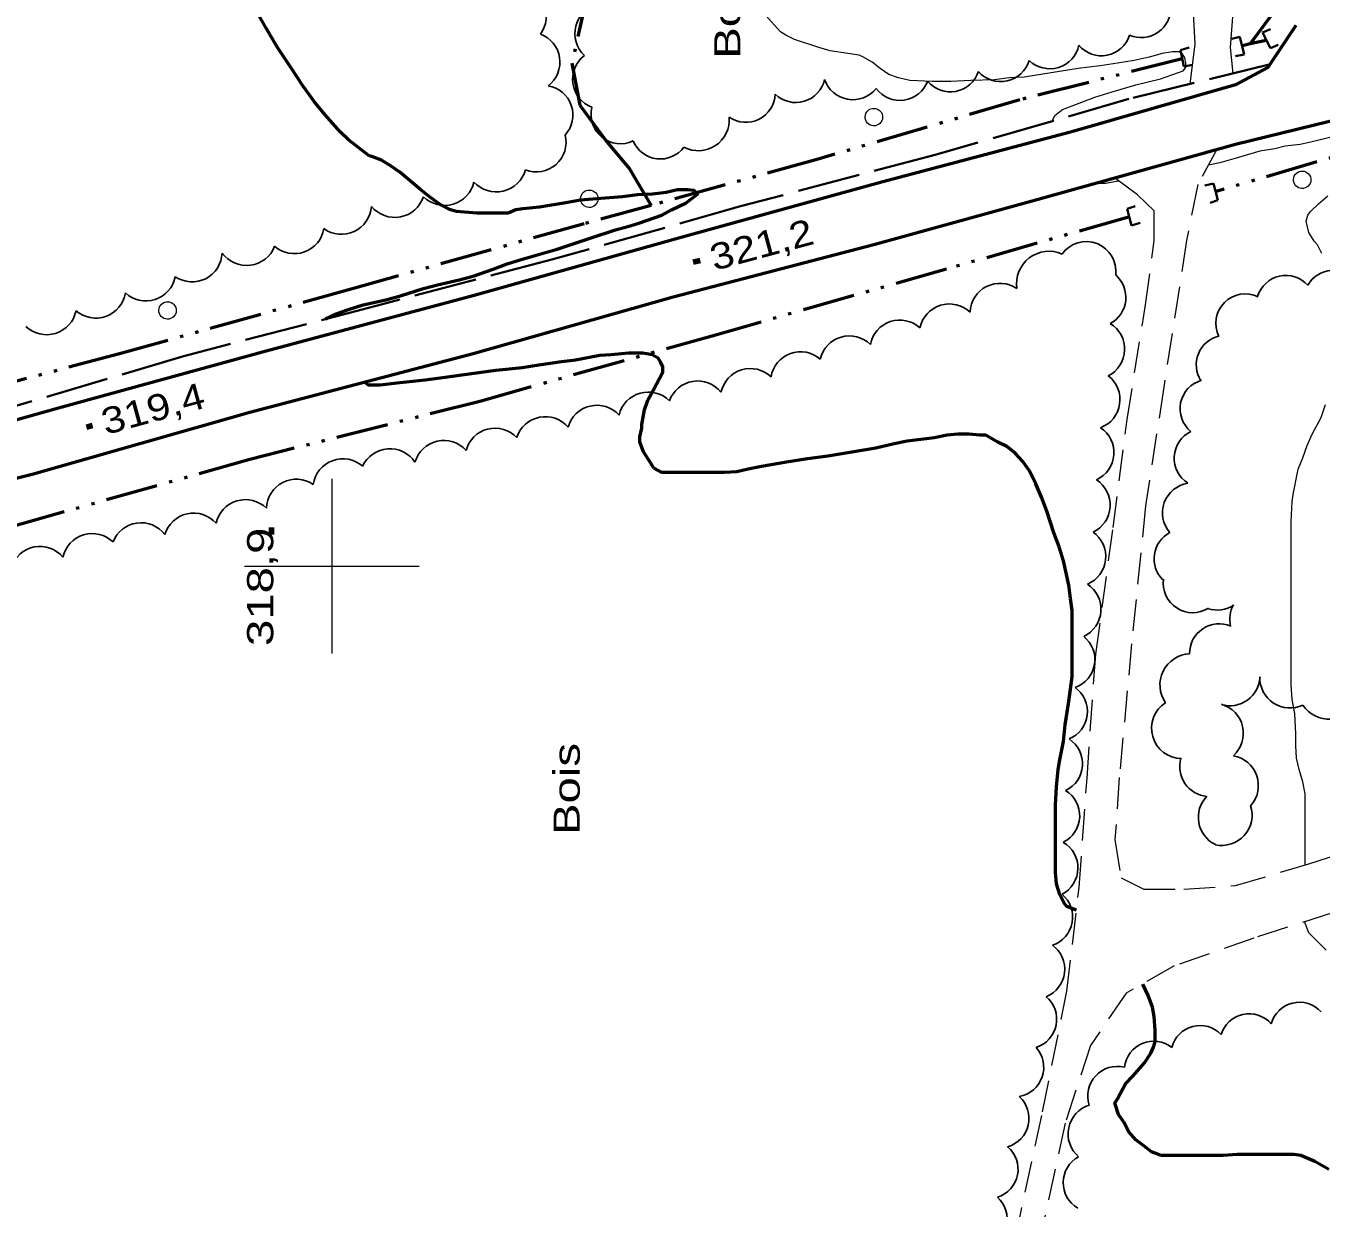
# Model space of a CAD drawing. Extents: x 240591 to 242335, y 5323482 to 5326937.
# Drawn here: x 240765 to 240913.3, y 5324526.5 to 5324661.9 of the extents above; entities that cross this region are included whole.
import ezdxf
from ezdxf.enums import TextEntityAlignment as Align

# ---------------------------------------------------------------- set-up
doc = ezdxf.new("R2010")
doc.units = 0
doc.header["$LTSCALE"] = 1.2
for name, pattern in [('DASH_DOUBLE_DOT', [9.2, 5, -1.2, 0.3, -1.2, 0.3, -1.2]), ('LONG_DASHED', [7.5, 6, -1.5]), ('MEDIUM_DASHED', [4.5, 3, -1.5])]:
    doc.linetypes.add(name, pattern=pattern)
for name, color, linetype, lineweight in [('1', 7, 'Continuous', 53), ('19', 7, 'Continuous', 13), ('2', 7, 'Continuous', 13), ('21', 7, 'Continuous', 53), ('26', 7, 'Continuous', 35), ('3', 7, 'Continuous', 140), ('36', 7, 'Continuous', 13), ('4', 7, 'DASH_DOUBLE_DOT', 53), ('44', 7, 'Continuous', 25), ('61', 7, 'Continuous', 13)]:
    doc.layers.add(name, color=color, linetype=linetype, lineweight=lineweight)

msp = doc.modelspace()

# ---------------------------------------------------------------- linework, layer by layer
at = {"layer": '1', "linetype": 'LONG_DASHED'}
for points in [[(240804.3, 5324647), (240801.9, 5324648.8), (240801, 5324649.7), (240799.2, 5324651.7), (240798, 5324653.2), (240796.7, 5324655), (240795.3, 5324657.1), (240793.8, 5324659.4), (240792.5, 5324661.6), (240790.8, 5324664.6)], [(240821.1, 5324640.8), (240820.2, 5324640.4), (240819.5, 5324640.4), (240816.6, 5324640.4), (240814.3, 5324640.6), (240813.6, 5324640.8), (240812.4, 5324641.4), (240811.3, 5324642.2), (240810.2, 5324643.1), (240807.8, 5324645.1), (240806.8, 5324645.8), (240805.7, 5324646.5), (240804.6, 5324646.9), (240804.3, 5324647)], [(240884.8, 5324591.9), (240884.8, 5324594.9), (240884.6, 5324596.3), (240884.4, 5324597.8), (240883.8, 5324600.6), (240883.3, 5324602.2), (240882.7, 5324603.8), (240881.9, 5324606.3), (240881.3, 5324607.9), (240880.6, 5324609.5), (240879.9, 5324610.9), (240879.1, 5324612), (240878.3, 5324612.9), (240877.3, 5324613.7), (240876.3, 5324614.2), (240874.9, 5324615), (240874.2, 5324615), (240873, 5324615.1), (240871.7, 5324615.1), (240870.5, 5324615), (240869, 5324614.7), (240865.9, 5324614.3), (240864.4, 5324614), (240862.3, 5324613.5), (240859.8, 5324613.1), (240856.8, 5324612.6), (240854.5, 5324612.3), (240852.1, 5324611.9), (240849.2, 5324611.4), (240847.7, 5324611.1), (240846.4, 5324610.8), (240845, 5324610.7), (240843.6, 5324610.7), (240840.6, 5324610.7), (240837.8, 5324610.7), (240836.9, 5324611.2), (240836.6, 5324611.7), (240835.7, 5324613.1), (240835.3, 5324614.2), (240835.3, 5324614.8), (240835.5, 5324615.8), (240835.5, 5324616.2)], [(240914.2, 5324530.9), (240912.6, 5324531.8), (240911, 5324532.5), (240910.2, 5324532.6), (240909.3, 5324532.6), (240906.6, 5324532.6), (240903.7, 5324532.6), (240902.1, 5324532.5), (240900.6, 5324532.5), (240897.8, 5324532.5), (240895, 5324532.5), (240894.5, 5324532.7), (240893.9, 5324532.9), (240893, 5324533.6), (240892.1, 5324534.3), (240891.3, 5324535.2), (240890.7, 5324536.3), (240890.1, 5324537.2)]]:
    msp.add_lwpolyline(points, dxfattribs=at)
at = {"layer": '1'}
for points in [[(240799.3, 5324628.3), (240800.5, 5324628.9), (240801.9, 5324629.4), (240803.6, 5324629.9), (240806.2, 5324630.5), (240808, 5324631), (240810.5, 5324631.8), (240812.1, 5324632.2), (240814.6, 5324632.8), (240816.2, 5324633.2), (240818.5, 5324634), (240820.1, 5324634.6), (240821.7, 5324635.1), (240823.4, 5324635.6), (240825.8, 5324636.3), (240827.3, 5324636.8), (240829.7, 5324637.6), (240832.5, 5324638.5), (240833.9, 5324638.9), (240835.3, 5324639.3), (240837.8, 5324640.2), (240838.9, 5324640.8), (240840.6, 5324641.6), (240841.9, 5324642.6), (240841.5, 5324643), (240840.8, 5324643.1), (240839.6, 5324643.1), (240838.3, 5324642.8), (240836.7, 5324642.6), (240835, 5324642.5), (240833.3, 5324642.3), (240830.8, 5324642.1), (240828.5, 5324641.9), (240826.8, 5324641.6), (240823.8, 5324641.1), (240821.9, 5324640.9), (240821.1, 5324640.8)], [(240826.3, 5324623.4), (240823.7, 5324623), (240821.8, 5324622.7), (240818.8, 5324622.4), (240816, 5324622), (240813, 5324621.6), (240810.7, 5324621.3), (240807.8, 5324621), (240805.5, 5324620.7), (240804.2, 5324620.7), (240803.7, 5324621.1)], [(240835.5, 5324616.2), (240835.8, 5324617.9), (240836.2, 5324619), (240836.8, 5324620.1), (240837.9, 5324622.2), (240837.9, 5324622.8), (240837.7, 5324623.3), (240837.4, 5324623.8), (240836.7, 5324624.2), (240836.1, 5324624.3), (240835.6, 5324624.4), (240834, 5324624.4), (240832, 5324624.2), (240830.7, 5324624.1), (240827.9, 5324623.6), (240826.3, 5324623.4)], [(240885.3, 5324560.6), (240884.2, 5324561), (240883.9, 5324561.4), (240883.4, 5324562.4), (240883, 5324563.6), (240882.9, 5324564.9), (240882.9, 5324566.7), (240882.9, 5324569.5), (240882.9, 5324572.6), (240883, 5324574.7), (240883.2, 5324576.7), (240883.4, 5324577.8), (240883.8, 5324579.9), (240884, 5324581.8), (240884.4, 5324584.5), (240884.8, 5324587.3), (240884.8, 5324588.8), (240884.8, 5324591.6), (240884.8, 5324591.9)], [(240890.1, 5324537.2), (240889.7, 5324538.5), (240890, 5324539), (240890.9, 5324540.7), (240891.8, 5324541.6), (240893.1, 5324543.1), (240893.8, 5324544.2), (240894.1, 5324544.9), (240894.3, 5324545.5), (240894.3, 5324546.8), (240894.2, 5324548.4), (240894, 5324549.5), (240893.5, 5324550.8), (240892.9, 5324552.1)]]:
    msp.add_lwpolyline(points, dxfattribs=at)
at = {"layer": '19'}
msp.add_lwpolyline([(240898.3, 5324655.2), (240898.9, 5324659.8), (240898.6, 5324665.5), (240903.4, 5324666), (240902.9, 5324659.4), (240903.2, 5324656.4)], dxfattribs=at)
at = {"layer": '19', "linetype": 'MEDIUM_DASHED'}
for points in [[(240901.4, 5324647.8), (240899.2, 5324643.7), (240897.9, 5324637.3), (240895.3, 5324620.5), (240893.2, 5324606.9), (240891.6, 5324591.1), (240890.2, 5324575.8), (240889.7, 5324568.7), (240890.4, 5324564.3), (240893, 5324563), (240897.6, 5324563), (240903.5, 5324563.4), (240911.9, 5324565.9), (240921.9, 5324569.1)], [(240857.3, 5324402.1), (240859.2, 5324416.9), (240860.8, 5324430.9), (240861.2, 5324443.5), (240863.4, 5324457.3), (240866.1, 5324468.8), (240868.9, 5324481.2), (240872.2, 5324493.8), (240875.2, 5324506.7), (240878.3, 5324523), (240881.4, 5324537.5), (240884.2, 5324551.3), (240885.6, 5324563.2), (240886.5, 5324575.7), (240887.5, 5324589.9), (240889.5, 5324604.4), (240891.1, 5324616.8), (240893.2, 5324629.9), (240894.2, 5324637.3), (240894.2, 5324640.7), (240892.3, 5324642.5), (240889.6, 5324644.5)], [(240938.5, 5324566.7), (240926.7, 5324563.8), (240914.6, 5324560.3), (240905.6, 5324557.4), (240896.5, 5324554.2), (240891, 5324551.1), (240886.9, 5324545.1), (240884, 5324536.2), (240881.6, 5324525.1), (240879.4, 5324512.5), (240878, 5324503.1), (240876.1, 5324494.7), (240873.2, 5324483.1), (240872.2, 5324473.4), (240870.9, 5324466.3), (240867.9, 5324457.5), (240865.7, 5324445.8), (240864.5, 5324432.3), (240863.1, 5324419.4), (240861.1, 5324406.3)]]:
    msp.add_lwpolyline(points, dxfattribs=at)
at = {"layer": '2'}
for points in [[(240882.7, 5324651), (240882.6, 5324651.1), (240882.8, 5324651.6), (240883.2, 5324651.9), (240883.7, 5324652.3), (240884.8, 5324652.7), (240887.4, 5324653.7), (240889.4, 5324654.3), (240892.1, 5324655.1), (240894.9, 5324655.8), (240897.5, 5324656.7), (240897.8, 5324657.1), (240897.8, 5324657.6), (240897.7, 5324658.2), (240897.4, 5324658.7), (240897, 5324658.9), (240896.3, 5324658.9), (240895.1, 5324658.7), (240893.6, 5324658.3), (240891.9, 5324657.9), (240890, 5324657.6), (240888, 5324657.3), (240885.5, 5324657), (240882.4, 5324656.5), (240879.3, 5324656), (240877.6, 5324655.9), (240875.9, 5324655.7), (240873.2, 5324655.6), (240870.9, 5324655.5), (240868.8, 5324655.5), (240866.2, 5324655.6), (240864.9, 5324655.9), (240863.8, 5324656.3), (240862.8, 5324657), (240861.9, 5324657.7), (240860.9, 5324658.3), (240860.4, 5324658.5), (240859.1, 5324658.7), (240857.1, 5324659), (240855.8, 5324659.4), (240853, 5324660.3), (240852, 5324660.8), (240851.4, 5324661.2), (240851, 5324661.6), (240849.4, 5324663.4)], [(240914.3, 5324649.1), (240912.3, 5324648.6), (240910.9, 5324648.3), (240909.2, 5324648.1), (240908, 5324647.8), (240906.3, 5324647.5)], [(240906.3, 5324647.5), (240903.6, 5324646.7), (240901.7, 5324646.2), (240900.4, 5324645.9)], [(240890.1, 5324644.1), (240888.6, 5324643.8), (240887.2, 5324643.8)], [(240913.4, 5324635.8), (240912.9, 5324636.8), (240912.5, 5324637.2), (240911.9, 5324638.2), (240911.6, 5324639.5), (240911.8, 5324640.2), (240912.1, 5324640.6), (240913, 5324641.5), (240914.1, 5324642.4)], [(240911.5, 5324565.8), (240911.5, 5324568.8), (240911.5, 5324571.3), (240911.5, 5324573.9), (240911.2, 5324575.3), (240910.8, 5324576.7), (240910.5, 5324578), (240910.4, 5324579.4), (240910.4, 5324580.8), (240910.3, 5324583.1), (240910, 5324584.7), (240909.9, 5324586.4), (240909.9, 5324588.1), (240909.9, 5324591.1), (240909.9, 5324593.7), (240909.9, 5324596.9), (240909.9, 5324599.6), (240909.9, 5324602.5), (240909.9, 5324605.1), (240910, 5324607.4), (240910.1, 5324608.2), (240910.7, 5324611.1), (240911.2, 5324612.4), (240911.7, 5324613.8), (240912.3, 5324615.1), (240913.3, 5324617), (240913.8, 5324618.5)], [(240913.9, 5324556), (240911.9, 5324558), (240911.4, 5324559.3)]]:
    msp.add_lwpolyline(points, dxfattribs=at)
at = {"layer": '21'}
for points in [[(240910.4, 5324661.9), (240907.2, 5324657.1), (240903.5, 5324655.1), (240884.6, 5324649.7), (240863.1, 5324644), (240840.3, 5324637.7), (240816.3, 5324631), (240792.5, 5324624.6), (240768.7, 5324618.1), (240744.5, 5324611.3), (240717.6, 5324604), (240694.3, 5324597.5), (240669.7, 5324591), (240649, 5324585.6), (240630.8, 5324580.6), (240610.8, 5324574.8)], [(240941.8, 5324658.1), (240924.9, 5324653.5), (240903.5, 5324648.3), (240880.9, 5324642), (240862.1, 5324636.8), (240839.1, 5324630.8), (240816.2, 5324624.3), (240790.6, 5324617.6), (240765.7, 5324610.5), (240737.8, 5324603.5), (240706.7, 5324594.4), (240678.6, 5324586.6), (240650.6, 5324578.9), (240620.6, 5324570.1), (240610.8, 5324567.5)]]:
    msp.add_lwpolyline(points, dxfattribs=at)
at = {"layer": '21', "linetype": 'LONG_DASHED', "lineweight": 35}
msp.add_lwpolyline([(240907.5, 5324657.5), (240891.3, 5324653.5), (240869.1, 5324647.1), (240846.8, 5324641.2), (240825.2, 5324635.1), (240805.8, 5324630), (240782.9, 5324624), (240763.7, 5324618.3), (240745.5, 5324613.4), (240728.3, 5324608.7), (240710.6, 5324603.9), (240687, 5324597.4), (240666.3, 5324592), (240647.4, 5324587), (240631.1, 5324582.9), (240614.9, 5324578.2), (240610.8, 5324577.1)], dxfattribs=at)
at = {"layer": '26'}
for p, q in [((240904, 5324660.6), (240903.1, 5324660.4)), ((240904, 5324660.6), (240904.5, 5324658.6)), ((240906.6, 5324661.1), (240907.5, 5324661.5)), ((240907.5, 5324659.3), (240906.6, 5324661.1)), ((240897.2, 5324659.1), (240898.2, 5324659.4)), ((240897.6, 5324657.2), (240897.2, 5324659.1)), ((240907.5, 5324659.3), (240908.4, 5324659.7)), ((240904.5, 5324658.6), (240903.5, 5324658.4)), ((240897.6, 5324657.2), (240898.6, 5324657.4)), ((240901, 5324643.8), (240900, 5324643.6)), ((240901, 5324643.8), (240901.5, 5324641.9)), ((240891.1, 5324640.9), (240892, 5324641.2)), ((240901.5, 5324641.9), (240900.6, 5324641.6)), ((240891.6, 5324639), (240891.1, 5324640.9)), ((240891.6, 5324639), (240892.6, 5324639.3))]:
    msp.add_line(p, q, dxfattribs=at)
at = {"layer": '3'}
for p, q in [((240841.4, 5324634.8), (240842.2, 5324635)), ((240771.9, 5324615.9), (240772.6, 5324616.1)), ((240793.1, 5324603.6), (240793.1, 5324604.4))]:
    msp.add_line(p, q, dxfattribs=at)
at = {"layer": '36'}
for centre in [(240862.093, 5324651.42), (240911.143, 5324644.24), (240829.493, 5324642.07), (240781.193, 5324629.27)]:
    msp.add_ellipse(centre, major_axis=(0.23, 0.973), ratio=0.999999, dxfattribs=at)
at = {"layer": '4'}
msp.add_line((240923.4, 5324649.4), (240901.3, 5324642.9), dxfattribs=at)
for points in [[(240838.1, 5324695.3), (240833.5, 5324685.9), (240831.9, 5324674.9), (240829.5, 5324666.5), (240827.5, 5324657.6), (240828.4, 5324652.8), (240831.5, 5324648.6), (240834.1, 5324645.5), (240836.6, 5324641.3)], [(240907.9, 5324673.3), (240909, 5324667.1), (240908.6, 5324664.4), (240905.2, 5324659.8)], [(240907, 5324660.2), (240905.2, 5324659.8), (240904.3, 5324659.6)], [(240897.4, 5324658.1), (240878.8, 5324653.4), (240855.7, 5324646.6), (240836.6, 5324641.3)], [(240836.6, 5324641.3), (240828.9, 5324639.2), (240802.5, 5324631.8), (240775.7, 5324624.3), (240749.7, 5324617.4), (240726.6, 5324610.7), (240697.5, 5324602.4), (240672.5, 5324595.7), (240648.5, 5324589.2), (240622.8, 5324582.6), (240610.8, 5324579.1)], [(240891.4, 5324640), (240870.4, 5324634), (240844.1, 5324626.5), (240817.1, 5324618.9), (240790.6, 5324612.2), (240764.4, 5324604.8), (240735.9, 5324597), (240712, 5324590.2), (240683.1, 5324582.1), (240659.8, 5324576.3), (240638.9, 5324570.6), (240615.8, 5324564.2), (240610.8, 5324562.7)]]:
    msp.add_lwpolyline(points, dxfattribs=at)
at = {"layer": '44'}
for centre, radius, start, end in [((240859.675, 5324656.844), 3.434, 199.10656, 321.15366), ((240853.696, 5324621.113), 3.432, 48.93804, 170.65251), ((240886.843, 5324619.061), 3.434, 290.75961, 52.35845), ((240901.411, 5324598.328), 3.371, 252.19671, 304.04053), ((240901.625, 5324590.015), 3.375, 66.69457, 180.92987), ((240905.068, 5324545.376), 3.349, 41.14441, 163.27718), ((240887.138, 5324529.385), 3.368, 118.31819, 239.928)]:
    msp.add_arc(centre, radius, start, end, dxfattribs=at)
for centre, major_axis, ratio, start_param, end_param in [((240821.14, 5324662.926), (2.651, 2.155), 0.999159, 4.9761344, 7.0809743), ((240831.319, 5324660.985), (-3.359, 0.866), 0.999995, 5.2210176, 7.3467234), ((240892.725, 5324663.873), (3.31, 0.64), 0.992679, 4.1123932, 6.1500355), ((240822.677, 5324657.718), (3.424, 0.455), 0.994847, 5.2429491, 7.3575194), ((240888.149, 5324661.847), (0.681, -3.335), 0.997007, 5.213403, 7.3405337), ((240882.235, 5324660.348), (0.736, 3.317), 0.999983, 2.5940873, 4.7238028), ((240831.016, 5324655.745), (-3.395, -0.498), 0.999978, 5.2201366, 7.3432441), ((240876.626, 5324658.881), (1.004, 3.247), 0.999983, 2.5903809, 4.719348), ((240870.853, 5324657.695), (1.081, 3.209), 0.999983, 2.5895834, 4.7203146), ((240824.204, 5324651.655), (3.414, 0.065), 0.997804, 5.5254828, 7.6595814), ((240853.146, 5324656.467), (0.987, -3.234), 0.995158, 5.2146375, 7.3362002), ((240865.068, 5324656.74), (2.658, 2.127), 0.999995, 3.1130891, 5.2450467), ((240847.423, 5324654.201), (1.516, -3.022), 0.999994, 5.223975, 7.3443576), ((240833.054, 5324651.732), (1.558, -2.988), 0.995781, 3.9913473, 6.2504771), ((240841.973, 5324651.135), (-0.243, 3.558), 0.999985, 2.5944412, 4.7184284), ((240823.423, 5324648.535), (3.411, -0.091), 0.992003, 4.3690498, 6.5567635), ((240837.62, 5324649.972), (3.109, -1.303), 0.992639, 3.932197, 6.0420242), ((240818.847, 5324646.319), (0.806, -3.379), 0.999734, 5.2172321, 7.3460742), ((240812.929, 5324644.739), (0.961, -3.299), 0.999729, 5.2184426, 7.3478998), ((240801.116, 5324641.441), (1.318, -3.186), 0.998307, 5.2645463, 7.389184), ((240807.222, 5324643.396), (2.612, 2.277), 0.999995, 3.1148024, 5.2443213), ((240795.711, 5324639.216), (1.073, -3.272), 0.996938, 5.2504306, 7.3727828), ((240886.406, 5324633.758), (-3.374, 0.442), 0.999752, 3.1463171, 5.7918037), ((240784.004, 5324635.991), (1.465, -3.12), 0.99695, 5.2492395, 7.3753008), ((240790.237, 5324637.901), (0.102, -3.468), 0.999604, 5.315452, 7.4463906), ((240882.151, 5324632.32), (-2.275, 2.956), 0.999831, 5.2163857, 7.3433658), ((240914.696, 5324630.49), (1.354, 3.089), 0.999717, 5.7685394, 7.7445997), ((240778.707, 5324633.803), (0.698, 3.366), 0.999984, 2.5947931, 4.7229149), ((240876.529, 5324628.942), (-1.535, 3.07), 0.99995, 5.2221159, 7.3502156), ((240887.54, 5324630.771), (3.118, -1.383), 0.999268, 5.6245979, 7.5526741), ((240909.274, 5324629.911), (-3.239, -0.955), 0.999984, 3.5852331, 5.7109626), ((240772.967, 5324631.829), (1.173, -3.229), 0.999862, 5.2175388, 7.3478928), ((240904.633, 5324627.801), (0.486, -3.34), 0.999891, 2.5521962, 5.0272965), ((240870.739, 5324626.574), (-0.875, 3.334), 0.998491, 5.2702994, 7.3912354), ((240767.341, 5324629.932), (-0.081, -3.439), 0.999961, 5.5462353, 7.6749152), ((240865.067, 5324624.727), (-1.116, 3.26), 0.997067, 5.2181883, 7.3373191), ((240859.288, 5324622.927), (-0.839, 3.328), 0.997653, 5.2581395, 7.3803182), ((240887.38, 5324624.836), (3.43, -0.127), 0.999727, 5.2210481, 7.3457296), ((240902.382, 5324623.055), (-1.204, -3.151), 0.999857, 3.7403649, 5.6499383), ((240847.938, 5324619.187), (-0.852, 3.33), 0.998486, 5.2694821, 7.3947573), ((240841.897, 5324617.765), (-0.399, 3.409), 0.998483, 5.267349, 7.3944323), ((240900.532, 5324618.023), (-2.881, 1.763), 0.998543, 5.5356324, 7.7191188), ((240836.245, 5324616.498), (-0.774, 3.344), 0.998291, 5.2689626, 7.3938853), ((240830.372, 5324614.982), (-0.277, 3.419), 0.999828, 5.3693928, 7.4992082), ((240818.695, 5324612.364), (-0.848, 3.325), 0.999861, 5.2193835, 7.3430049), ((240824.463, 5324613.671), (-0.299, 3.425), 0.999684, 5.3347501, 7.4568214), ((240812.829, 5324610.956), (-0.978, -3.289), 0.999984, 2.5921483, 4.7228262), ((240886.159, 5324612.999), (3.405, -0.428), 0.998293, 5.2641228, 7.39163), ((240899.881, 5324612.355), (-3.391, 0.195), 0.999312, 5.2209654, 7.3454826), ((240806.663, 5324609.999), (0.044, 3.441), 0.999496, 5.3104217, 7.4346882), ((240801.281, 5324608.83), (-0.088, 3.451), 0.999962, 5.5441642, 7.6742769), ((240795.952, 5324606.512), (-1.563, 3.058), 0.99995, 5.2180112, 7.3470418), ((240885.716, 5324606.991), (3.412, -0.438), 0.99913, 5.2857465, 7.4089731), ((240898.588, 5324606.084), (-3.133, 1.44), 0.99939, 5.2967004, 7.4268398), ((240790.122, 5324604.16), (-1.012, 3.297), 0.99757, 5.2139717, 7.340639), ((240784.185, 5324602.626), (0.371, 3.416), 0.999961, 5.5438925, 7.6747056), ((240778.153, 5324601.534), (-0.485, 3.395), 0.9998, 5.2168517, 7.3466906), ((240772.565, 5324600.284), (-0.853, 3.336), 0.997887, 5.265317, 7.3857989), ((240885.221, 5324601.09), (3.409, -0.369), 0.9998, 5.2181724, 7.3466206), ((240897.553, 5324600.845), (-2.459, -2.313), 0.999388, 4.4427444, 6.3278478), ((240766.583, 5324598.818), (-0.653, 3.372), 0.999861, 5.220941, 7.3452499), ((240898.611, 5324598.03), (0.695, -3.303), 0.99965, 4.3668753, 6.6333649), ((240884.662, 5324595.06), (3.429, -0.234), 0.999444, 5.2188304, 7.3405181), ((240906.221, 5324593.912), (0.986, -3.225), 0.999777, 3.9043967, 4.6553542), ((240884.005, 5324589.29), (3.294, -0.842), 0.999485, 5.3059451, 7.4325454), ((240898.44, 5324586.379), (-3.066, 1.862), 0.999536, 5.3109636, 7.4338166), ((240902.856, 5324587.469), (1.702, -3.024), 0.997067, 5.4863459, 7.2948963), ((240909.758, 5324587.219), (2.778, -2.075), 0.999866, 3.7585603, 5.7923637), ((240883.161, 5324583.342), (3.369, -0.398), 0.999795, 5.2164743, 7.345189), ((240897.358, 5324581.423), (1.976, -2.845), 0.999742, 3.1039872, 5.6674265), ((240900.944, 5324580.841), (1.683, 3.025), 0.999588, 4.3868591, 6.5119023), ((240914.217, 5324586.031), (0.263, -3.57), 0.995686, 5.2153772, 7.3388319), ((240882.584, 5324577.355), (3.384, -0.354), 0.997836, 5.2616927, 7.3809501), ((240900.583, 5324577.058), (-1.499, -3.127), 0.999608, 4.8888784, 6.6270052), ((240902.659, 5324574.866), (3.282, 1.12), 0.999995, 5.2228706, 7.3480795), ((240882.267, 5324571.4), (3.393, -0.146), 0.999722, 5.2170924, 7.3441871), ((240902.713, 5324571.216), (1.241, -3.235), 0.99976, 3.5753987, 5.4639837), ((240901.936, 5324571.477), (2.402, 2.509), 0.999761, 3.6899031, 5.7898964), ((240882.054, 5324565.424), (3.382, -0.407), 0.999589, 5.3163033, 7.4423543), ((240881.463, 5324559.804), (3.337, -0.632), 0.999722, 5.2191143, 7.3455385), ((240880.55, 5324553.823), (3.37, -0.407), 0.999977, 5.2191947, 7.3512093), ((240879.639, 5324548.097), (-1.112, 3.2), 0.999994, 3.1162991, 5.2451097), ((240910.834, 5324546.677), (-0.798, 3.272), 0.999948, 5.217815, 7.3432884), ((240899.444, 5324544.027), (-0.85, 3.242), 0.99742, 5.2187476, 7.3408203), ((240878.136, 5324542.593), (3.018, -1.581), 0.999825, 5.3729416, 7.4978561), ((240894.138, 5324542.237), (-0.825, 3.256), 0.99982, 5.3702597, 7.4974963), ((240889.973, 5324539.314), (-2.472, 2.317), 0.999977, 5.2189336, 7.3494834), ((240876.454, 5324536.745), (3.32, -0.725), 0.994152, 5.2112121, 7.3297647), ((240887.782, 5324534.975), (1.121, -3.265), 0.999995, 3.1143151, 5.2457102), ((240875.213, 5324530.929), (3.305, -0.762), 0.996288, 5.2489471, 7.3750982), ((240873.979, 5324525.193), (-1.013, 3.235), 0.999995, 3.1133106, 5.2457526)]:
    msp.add_ellipse(centre, major_axis=major_axis, ratio=ratio, start_param=start_param, end_param=end_param, dxfattribs=at)
at = {"layer": '61'}
for points in [[(240800, 5324610), (240800, 5324600), (240800, 5324590)], [(240790, 5324600), (240800, 5324600), (240810, 5324600)]]:
    msp.add_lwpolyline(points, dxfattribs=at)

# ---------------------------------------------------------------- texts
at = {"layer": '3', "width": 1.2}
for s, rotation, p in [('321,2', 15.068, (240843.8, 5324633.8)), ('319,4', 15.256, (240774.1, 5324615))]:
    msp.add_text(s, height=3, rotation=rotation, dxfattribs=at).set_placement(p)
at = {"layer": '3', "width": 1.35}
msp.add_text('318,9', height=3, rotation=90, dxfattribs=at).set_placement((240793.3, 5324604.4), align=Align.RIGHT)
at = {"layer": '44', "width": 1.35}
for p in [(240846.8, 5324658.1), (240828.4, 5324569.2)]:
    msp.add_text('Bois', height=3, rotation=90, dxfattribs=at).set_placement(p)

doc.saveas('drawing.dxf')
